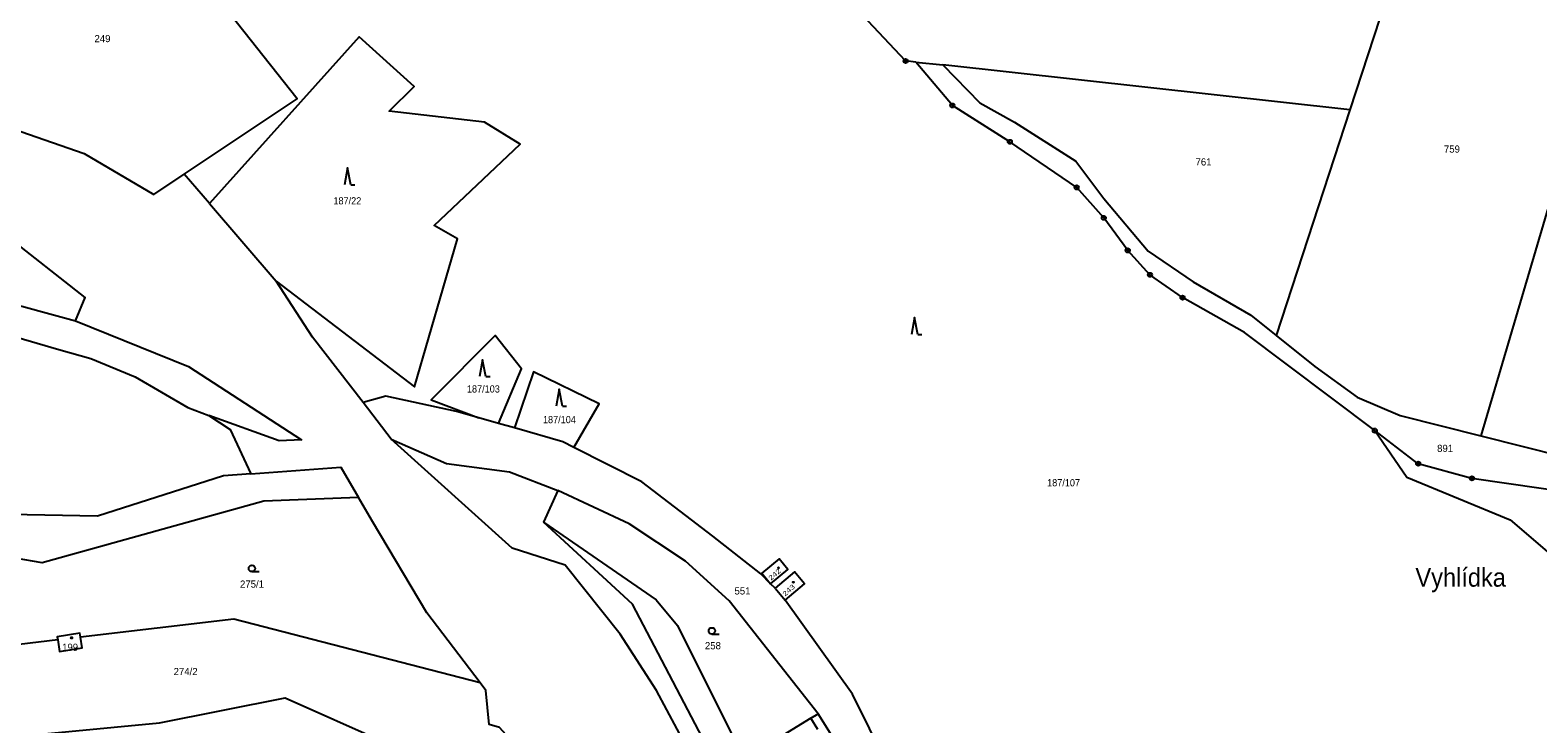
# Model space of a CAD drawing. Extents: x -754445 to -751443, y -1030748 to -1028224.
# Drawn here: x -753236 to -752878.6, y -1029401.4 to -1029236.8 of the extents above; entities that cross this region are included whole.
import ezdxf
from ezdxf.enums import TextEntityAlignment as Align

# ---------------------------------------------------------------- set-up
doc = ezdxf.new("R2010")
doc.units = 0
doc.header["$LTSCALE"] = 0.68
for name, color, linetype, lineweight in [('1', 7, 'Continuous', 25), ('3', 7, 'Continuous', 25), ('5', 7, 'Continuous', 25), ('7', 7, 'Continuous', 13), ('8', 7, 'Continuous', 25)]:
    doc.layers.add(name, color=color, linetype=linetype, lineweight=lineweight)
doc.layers.add('2', color=7, linetype='Continuous')

msp = doc.modelspace()

# ---------------------------------------------------------------- linework, layer by layer
at = {"layer": '1'}
for p, q in [((-753026.04, -1029244.41), (-753019.67, -1029245.11)), ((-752923.17, -1029255.77), (-753019.67, -1029245.11)), ((-752923.17, -1029255.77), (-752940.65, -1029309.29)), ((-753193.54, -1029277.97), (-753199.5, -1029271.03)), ((-753193.54, -1029277.97), (-753177.73, -1029296.4)), ((-753275.33, -1029292.14), (-753225.25, -1029305.78)), ((-753150.41, -1029333.89), (-753157.12, -1029325.18)), ((-753110.97, -1029346), (-753114.37, -1029353.55)), ((-753059.42, -1029369.21), (-753057.08, -1029372)), ((-753229.51, -1029381.44), (-753238.61, -1029382.51)), ((-753050.93, -1029400), (-753049.22, -1029398.96))]:
    msp.add_line(p, q, dxfattribs=at)
for points in [[(-752845.58, -1029166.38), (-752850.68, -1029190.24), (-752852.46, -1029198.42), (-752892.15, -1029333.05)], [(-752903.32, -1029194.79), (-752903.88, -1029196.7), (-752904.75, -1029199.37), (-752923.17, -1029255.77)], [(-753199.5, -1029271.03), (-753172.72, -1029253.11), (-753216.96, -1029197.16)], [(-753026.04, -1029244.41), (-753028.48, -1029244.15), (-753043.67, -1029227.93), (-753044.85, -1029222.5)], [(-753177.73, -1029296.4), (-753144.94, -1029321.47), (-753134.72, -1029286.35), (-753140.28, -1029283.19), (-753119.9, -1029263.86), (-753128.31, -1029258.69), (-753150.92, -1029256.05), (-753144.96, -1029250.21), (-753158.07, -1029238.46), (-753193.54, -1029277.97)], [(-752917.26, -1029331.82), (-752948.16, -1029308.52), (-752962.83, -1029300.28), (-752970.56, -1029294.87), (-752975.83, -1029289.08), (-752981.5, -1029281.36), (-752987.93, -1029274.15), (-753003.77, -1029263.33), (-753017.41, -1029254.71), (-753026.04, -1029244.41)], [(-753019.67, -1029245.11), (-753010.87, -1029254.05), (-753002.64, -1029258.65), (-752988.15, -1029267.89), (-752981.52, -1029276.76), (-752970.99, -1029289.27), (-752960.32, -1029296.52), (-752946.68, -1029304.48), (-752940.65, -1029309.29)], [(-753253.36, -1029255.67), (-753223.22, -1029266.09), (-753206.72, -1029275.86), (-753199.5, -1029271.03)], [(-753225.25, -1029305.78), (-753223.01, -1029300.22), (-753241.88, -1029285.39)], [(-753157.12, -1029325.18), (-753169.07, -1029309.68), (-753177.73, -1029296.4)], [(-753273.35, -1029299.73), (-753229.21, -1029312.62), (-753221.68, -1029314.7), (-753211.16, -1029319.1), (-753198.69, -1029326.32), (-753193.68, -1029328.26)], [(-753225.25, -1029305.78), (-753198.46, -1029316.61), (-753171.7, -1029334.04), (-753177.03, -1029334.23), (-753193.68, -1029328.26)], [(-753124.99, -1029330.11), (-753119.57, -1029317.16), (-753125.79, -1029309.3), (-753140.95, -1029324.51), (-753129.63, -1029328.78)], [(-752940.65, -1029309.29), (-752931.46, -1029316.63), (-752921.44, -1029323.86), (-752911.21, -1029328.24), (-752892.15, -1029333.05)], [(-753107.14, -1029335.79), (-753101.1, -1029325.47), (-753116.73, -1029317.9), (-753121.22, -1029331.19)], [(-753129.63, -1029328.78), (-753134.93, -1029327.27), (-753151.71, -1029323.69), (-753157.12, -1029325.18)], [(-752892.15, -1029333.05), (-752862.98, -1029340.4), (-752832.2, -1029347.99), (-752815.94, -1029324.28)], [(-753193.68, -1029328.26), (-753188.61, -1029331.56), (-753183.7, -1029342.08)], [(-753121.22, -1029331.19), (-753124.99, -1029330.11), (-753129.63, -1029328.78)], [(-753183.7, -1029342.08), (-753190.21, -1029342.56), (-753220.07, -1029352.09), (-753245.1, -1029351.6), (-753287.81, -1029333.07)], [(-753071.76, -1029541.75), (-753071.63, -1029533.49), (-753068.15, -1029524.38), (-753063.28, -1029509.75), (-753064.12, -1029480.78), (-753067.4, -1029461.3), (-753067.68, -1029447.26), (-753071.53, -1029428.53), (-753075.28, -1029416.4), (-753087.55, -1029393.42), (-753096.16, -1029380.11), (-753109.22, -1029363.71), (-753121.76, -1029359.73), (-753150.41, -1029333.89)], [(-753150.41, -1029333.89), (-753137.34, -1029339.63), (-753122.41, -1029341.59), (-753110.97, -1029346)], [(-753107.14, -1029335.79), (-753109.75, -1029334.47), (-753121.22, -1029331.19)], [(-752806.54, -1029363.17), (-752834.17, -1029353.21), (-752844.35, -1029350.41), (-752894.22, -1029343.14), (-752906.97, -1029339.67), (-752917.26, -1029331.82)], [(-752917.26, -1029331.82), (-752909.67, -1029342.86), (-752885.15, -1029352.98), (-752854.27, -1029379.48), (-752855.62, -1029396.74)], [(-753059.42, -1029369.21), (-753060.49, -1029368.16), (-753062.84, -1029365.8), (-753074.19, -1029356.89), (-753091, -1029343.97), (-753107.14, -1029335.79)], [(-753183.7, -1029342.08), (-753162.42, -1029340.53), (-753158.2, -1029347.67)], [(-753158.2, -1029347.67), (-753180.6, -1029348.52), (-753233.22, -1029363.19), (-753239.55, -1029362.11)], [(-753129.37, -1029391.61), (-753142.02, -1029375.06), (-753154.84, -1029353.36), (-753158.2, -1029347.67)], [(-753049.22, -1029398.96), (-753070.34, -1029372.17), (-753080.69, -1029362.82), (-753094.01, -1029353.91), (-753110.97, -1029346)], [(-753071.76, -1029541.75), (-753060.01, -1029515.61), (-753055.07, -1029481.09), (-753056.44, -1029461.05), (-753060.62, -1029443.17), (-753073.13, -1029411.34), (-753093.21, -1029373.01), (-753114.37, -1029353.55)], [(-753114.37, -1029353.55), (-753087.64, -1029371.97), (-753082.58, -1029378.01), (-753066.77, -1029409.71)], [(-753057.08, -1029372), (-753052.46, -1029368.17), (-753054.81, -1029365.34), (-753059.42, -1029369.21)], [(-753024.97, -1029426.88), (-753041.08, -1029394.35), (-753057.08, -1029372)], [(-753129.37, -1029391.61), (-753187.72, -1029376.55), (-753224.09, -1029380.81)], [(-753224.09, -1029380.81), (-753224.25, -1029379.85), (-753229.63, -1029380.7), (-753229.51, -1029381.44)], [(-753229.51, -1029381.44), (-753229.07, -1029384.21), (-753223.69, -1029383.35), (-753224.09, -1029380.81)], [(-753120.06, -1029407.42), (-753124.78, -1029402.23), (-753127.23, -1029401.56), (-753127.98, -1029393.43), (-753129.37, -1029391.61)], [(-753237.62, -1029404.18), (-753205.38, -1029401.16), (-753175.6, -1029395.17), (-753151.79, -1029405.78), (-753120.06, -1029407.42)], [(-753049.27, -1029402.74), (-753050.93, -1029400), (-753066.77, -1029409.71)], [(-753019.37, -1029481.51), (-753017.38, -1029481.38), (-753022.02, -1029456.73), (-753030.47, -1029434.9), (-753038.4, -1029416.33), (-753049.22, -1029398.96)]]:
    msp.add_lwpolyline(points, dxfattribs=at)
msp.add_lwpolyline([(-753060.49, -1029368.16), (-753056.41, -1029364.78), (-753058.49, -1029362.27), (-753062.57, -1029365.65)], close=True, dxfattribs=at)
at = {"layer": '3'}
for p, q in [((-753160.04, -1029273.52), (-753159.044, -1029273.52)), ((-753025.61, -1029309), (-753024.614, -1029309)), ((-753128.01, -1029319.02), (-753127.014, -1029319.02)), ((-753109.85, -1029326.03), (-753108.854, -1029326.03)), ((-753183.463, -1029365.26), (-753181.713, -1029365.26)), ((-753074.423, -1029380.07), (-753072.673, -1029380.07))]:
    msp.add_line(p, q, dxfattribs=at)
for points in [[(-753160.04, -1029273.52), (-753160.79, -1029269.52), (-753161.54, -1029273.52)], [(-753025.61, -1029309), (-753026.36, -1029305), (-753027.11, -1029309)], [(-753128.01, -1029319.02), (-753128.76, -1029315.02), (-753129.51, -1029319.02)], [(-753109.85, -1029326.03), (-753110.6, -1029322.03), (-753111.35, -1029326.03)]]:
    msp.add_lwpolyline(points, dxfattribs=at)
for centre in [(-753183.4629, -1029364.5098), (-753074.4229, -1029379.3198)]:
    msp.add_circle(centre, 0.75, dxfattribs=at)
at = {"layer": '5'}
for centre, radius in [((-753058.6146, -1029364.3494), 0.1172), ((-753055.1046, -1029367.7994), 0.1172), ((-753226.2168, -1029380.9692), 0.175)]:
    msp.add_circle(centre, radius, dxfattribs=at)
at = {"layer": '8'}
for centre, radius in [((-753028.48, -1029244.1499), 0.5), ((-753028.48, -1029244.1499), 0.0303), ((-753017.41, -1029254.7099), 0.5), ((-753017.41, -1029254.7099), 0.0303), ((-753003.77, -1029263.3299), 0.5), ((-753003.77, -1029263.3299), 0.0303), ((-752987.93, -1029274.1499), 0.5), ((-752987.93, -1029274.1499), 0.0303), ((-752981.5, -1029281.3599), 0.5), ((-752981.5, -1029281.3599), 0.0303), ((-752975.83, -1029289.0799), 0.5), ((-752975.83, -1029289.0799), 0.0303), ((-752970.56, -1029294.8699), 0.5), ((-752970.56, -1029294.8699), 0.0303), ((-752962.83, -1029300.2799), 0.5), ((-752962.83, -1029300.2799), 0.0303), ((-752917.26, -1029331.8199), 0.5), ((-752917.26, -1029331.8199), 0.0303), ((-752906.97, -1029339.6699), 0.5), ((-752906.97, -1029339.6699), 0.0303), ((-752894.22, -1029343.1399), 0.5), ((-752894.22, -1029343.1399), 0.0303)]:
    msp.add_circle(centre, radius, dxfattribs=at)

# ---------------------------------------------------------------- texts
at = {"layer": '2'}
for s, p in [('249', (-753218.889, -1029239.7)), ('759', (-752898.969, -1029265.896)), ('761', (-752957.859, -1029268.946)), ('891', (-752900.589, -1029336.886)), ('275/1', (-753183.44, -1029369.07)), ('551', (-753067.159, -1029370.69)), ('199', (-753226.559, -1029384.06)), ('258', (-753074.169, -1029383.68)), ('274/2', (-753199.18, -1029389.81))]:
    msp.add_text(s, height=1.7, dxfattribs=at).set_placement(p, align=Align.CENTER)
at = {"layer": '2', "width": 0.95}
for s, p in [('187/22', (-753160.839, -1029278.17)), ('187/103', (-753128.59, -1029322.79)), ('187/104', (-753110.56, -1029330.06)), ('187/107', (-752991.04, -1029345.03))]:
    msp.add_text(s, height=1.7, dxfattribs=at).set_placement(p, align=Align.CENTER)
at = {"layer": '2', "width": 1.3}
for s, rotation, p in [('242', 41, (-753059.1565, -1029366.3537)), ('243', 42, (-753055.8234, -1029370.1038))]:
    msp.add_text(s, height=1.14, rotation=rotation, dxfattribs=at).set_placement(p, align=Align.CENTER)
at = {"layer": '7', "width": 0.95}
msp.add_text('Vyhlídka', height=4.4, dxfattribs=at).set_placement((-752896.9, -1029368.838), align=Align.CENTER)

doc.saveas('drawing.dxf')
